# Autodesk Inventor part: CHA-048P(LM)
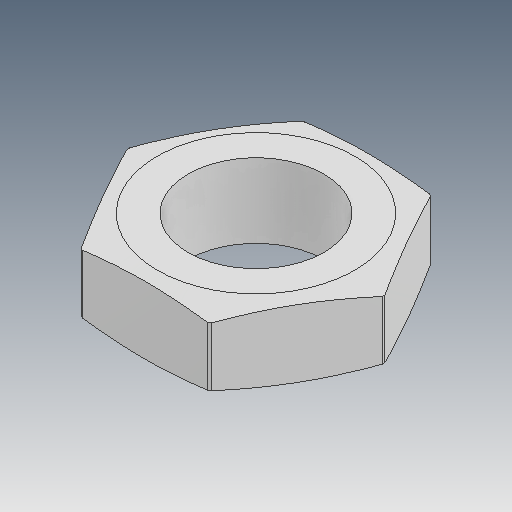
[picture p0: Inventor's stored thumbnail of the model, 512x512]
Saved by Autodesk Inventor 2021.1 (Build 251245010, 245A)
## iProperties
Created: 2021-05
Part Number: CHA-048P(LM)
Material: Ogólny
Document SubType Name: Modeling
Designer: user
Density: 1 g/cm^3
Appearance: Domyślna
Author: user
Revision Number: ÈÎºÎ
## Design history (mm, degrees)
feature "M18x1.5 ÂÝÎÆ¿×1"
node "Bryła1"
